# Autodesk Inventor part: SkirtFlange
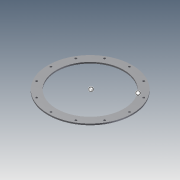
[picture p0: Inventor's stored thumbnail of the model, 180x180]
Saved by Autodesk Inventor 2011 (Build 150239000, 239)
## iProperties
Created: 2010-06
Part Number: SkirtFlange
Document SubType Name: Modeling
Designer: mklassen
Density: 1 g/cm^3
OD: 24.000 in
THK: 0.500 in
WDT: 3.000 in
BHN: 12.000 ul
BHD: 0.750 in
BCD: 14.000 in
Author: mklassen
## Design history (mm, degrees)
sketch "skSkirtFlange"
  geometry: C1 r 304.8 at (0, 0); C2 r 381 at (0, 0); 1 further point
  constraints: 2 centre point, 2 coincident
  dimensions: "d0" = 76.2 radial gap between concentric circles of C2 C1 (derived); "d1" = 609.6 diameter of C1 (derived)
extrude "SkirtFlange" new body sketch "skSkirtFlange" stored distance "d2" = 12.7 (derived); taper "d3" = 0 deg
sketch "skBoltHole"
  geometry: C1 r 304.8 at (0, 0) reference; 2 further points
  constraints: 1 coincident, 1 vertical alignment
  dimensions: "d7" = 355.6 distance of point (0, 355.6) point (0, 0) (= BCD)
hole "BoltHole" sketch "skBoltHole" at (0, 355.6) diameter "d8" = 19.05 (derived); stored, may be unused: countersink angle "d12" = 82 deg, drill point angle "d14" = 118 deg; dims "d9" = 19.05, "d10" = 9.525, "d11" = 6.35, "d13" = 25.4
pattern_circular "BoltCircle" dims angle "d16" = 360 deg
body "Solid1"
other parameters: "BCD" = 355.6 [user parameter; used in 2 equation terms], "d4" = 0, "d5" = 0, "d6" = 0
